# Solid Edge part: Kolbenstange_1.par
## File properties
Username: bmolnar
Dokumentum tartalom típus: 0
Author: bmolnar
Last saved by: bmolnar
Revision: 98
Sűrűség: 0,000 kg/m^3
Pontosság: 0,990
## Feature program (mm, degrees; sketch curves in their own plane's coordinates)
base feature "unnamed BaseFeature 1"
thread "unnamed Thread 1"
chamfer "Letörés_1"  SetBackValue2 = 20 deg
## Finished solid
Body 1: solid body, 21 faces, 32 edges, 14 vertices.
  Faces by surface: plane 8, cylinder 5, cone 4, torus 4
  Edges by curve: circle 17, line 9, curve on surface 4, ellipse 2
Bounding box of the edges (mm; curved faces can reach further): 50.000 x 50.000 x 2944.000, from (-25, -25, -86.5) to (25, 25, 2857.5).
Cylindrical faces by radius (mm): R6.75 x1, R8 x1, R9.75 x1, R10 x1, R25 x1
Conical faces (half-angle, radius in mm at the cone's reference point): 20 deg R8 x1, 30 deg R9.875 x1, 45 deg R24.25 x1, 60 deg R7.375 x1
Toroidal faces (ring radius, tube radius in mm): R7.15 r0.4 x2, R8.55 r1.2 x2
Planar faces by outward normal: +x 1, +z 3, -x 1, -z 1, oblique 2
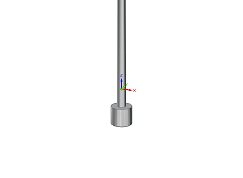
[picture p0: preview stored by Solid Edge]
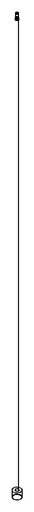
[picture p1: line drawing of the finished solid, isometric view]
